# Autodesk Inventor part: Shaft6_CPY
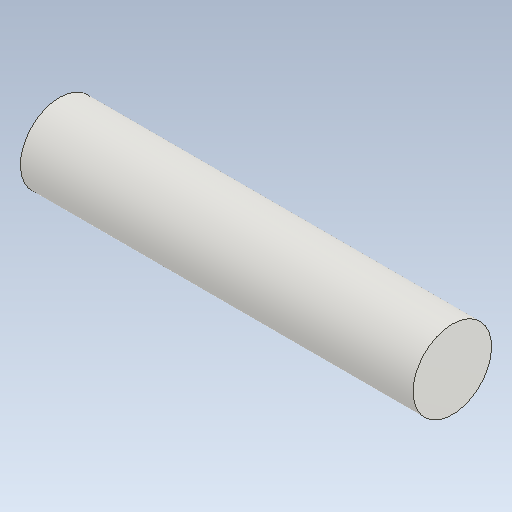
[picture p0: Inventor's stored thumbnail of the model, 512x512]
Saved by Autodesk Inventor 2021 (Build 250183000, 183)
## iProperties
Created: 2021-07
Part Number: Shaft6_CPY
Material: Steel
Document SubType Name: Modeling
Designer: CHIRAG
Density: 1 g/cm^3
Appearance: Plate
CustomPartVersion: 1
Author: CHIRAG
Length: 150.000 mm
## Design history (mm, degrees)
sketch "Main Sketch"
  geometry: L1 (0, 0)-(150, 0) reference; L2 (0, 0)-(0, 15); L3 (150, 15)-(150, 0); L4 (0, 15)-(150, 15)
  constraints: 8 end point, 3 horizontal, 2 vertical
  dimensions: "d3" = 30 diameter of L4 L1 (derived)
revolve "Revolution1" sketch "Main Sketch" stored, may be unused: angle "d4" = 0 deg
body "Solid1"
other parameters: "d0" = 0, "d1" = 0, "d2" = 0, "Length" = 150 [user parameter]
